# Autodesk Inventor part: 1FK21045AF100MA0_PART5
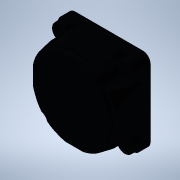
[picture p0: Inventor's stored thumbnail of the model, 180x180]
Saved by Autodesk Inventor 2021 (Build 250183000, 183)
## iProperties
Created: 2025-04
Part Number: 1FK21045AF100MA0_PART5
Material: Generic
Catalog Web Link: www.3dfindit.com
Description: -Servo synchronous motor
Document SubType Name: Modeling
Designer: psAdmin
Mass: 3.92604 g
Surface Area: 17.9521 cm^2
Volume: 3.92604 cm^3
Density: 1 g/cm^3
Appearance: PSOLRGB-48-56-69
Category: PARTsolutions
Title: 1FK21045AF100MA0_PART5
Author: Cadenas PARTsolutions
Comments: Servo synchronous motor
Sending System: PARTsolutions
Preprocessor: ST-DEVELOPER v19.3
PSOL_IDENT_0: {$CADENAS_DATA/23d-libs/siemens_ag/_cat_/52/6b/1fk21045af100ma0.prj},213 {VTYP=3D},{NB=1FK21045AF100
PSOL_IDENT_1: MA0_PART5},{LINA=1FK21045AF100MA0_PART5},{NN=1FK21045AF100MA0_PART5},{NOPRJ=TRUE},{DATE=19.08.2025 1
PSOL_IDENT_2: 4:00:38},{GEOMDATE=30.07.2025 02:01:45},{VERSION=},{LINEID=10},{WBVAR=},{WBNUMERIC=}  {NB=1FK21045AF
PSOL_IDENT_3: 100MA0_PART5},{LINA=1FK21045AF100MA0_PART5},{KT=DUMMY},{PREVIEW=../../../_pool_/cb/72/p_d211_xx_0043
PSOL_IDENT_4: 4j.png},{DESCSHORT=SIMOTICS S-1FK2 HD, SINAMICS S210 3AC 400V-480V, 2.4 Nm, 3000 rpm},{DESCLONG=SIMO
PSOL_IDENT_5: TICS S-1FK2 HD servo motor M0=2.4 Nm; PN = 0.75 kW at nN=3000 rpm (380-480 V); PN = 0.375 kW at nN=1
PSOL_IDENT_6: 500 rpm (200-240 V); with holding brake; degree of protection IP64; cylindrical shaft D19x40mm; abso
PSOL_IDENT_7: lute encoder 22-bit + 12-bit multiturn (encoder AM22DQC); with OCC interface; plug size M17, rotatab
PSOL_IDENT_8: le; SIMOTICS S-1FK2 servomotorfor a wide range of uses in industrial environments. SIMOTICS S‑1FK2 s
PSOL_IDENT_9: ervomotors are compact synchronous motors with a high dynamic performance that set themselves apart
PSOL_IDENT_10: as a result of their high power density, degree of protection and overload capability. The motors ar
PSOL_IDENT_11: e available in two variants: as High Dynamic variant (highest dynamic performance as a result of the
PSOL_IDENT_12: low intrinsic moment of inertia for applications demanding a high dynamic performance with low move
PSOL_IDENT_13: d masses) - and as Compact variant (precise and stable closed-loop control for medium up to large mo
PSOL_IDENT_14: ved masses as a result of a medium intrinsic moment of inertia). SIMOTICSS‑1FK2 servomotors fully ex
PSOL_IDENT_15: ploit their strengths in a system with the SINAMICSS210 frequency converter and simple connection us
PSOL_IDENT_16: ing the one cable connection (OCC). Advantages include the short control and positioning times, fast
PSOL_IDENT_17: and precise correction of disturbing quantities as well as stable control with a high dynamic perfo
PSOL_IDENT_18: rmance. The servo motors can be configured to address a wide range of requirements. For example with
PSOL_IDENT_19: and without holding brake, IP64 or IP65 degree of protection, singleturn or multiturn absolute enco
PSOL_IDENT_20: ders - to name just a few. Further, the servomotors are available in different shaft heights extendi
PSOL_IDENT_21: ng from 20 to 100. A shaft sealing ring is available to achieve an IP65 degree of protection and for
PSOL_IDENT_22: subsequent mounting at the motor or as spare part. SIMOTICS - the optimum motor for each and every
PSOL_IDENT_23: motion control application.},{INTNO=804766906411},{SUPPLIERALTNO=1FK2104-5AF10-0MA0},{MANUID=1FK2104
PSOL_IDENT_24: 5AF100MA0},{MANUNAME=Siemens},{MANUTYPEDESC=Synchronous motor 1FK2-HD 2.4 NM},{AAU732=SIMOTICS},{AAO
PSOL_IDENT_25: 057=S-1FK2},{AAU734=SIMOTICS S-1FK2 HD servo motor M0=2.4 Nm; PN = 0.75 kW at nN=3000 rpm (380-480 V
PSOL_IDENT_26: ); PN = 0.375 kW at nN=1500 rpm (200-240 V); with holding brake; degree of protection IP64; cylindri
PSOL_IDENT_27: cal shaft D19x40mm; absolute encoder 22-bit + 12-bit multiturn (encoder AM22DQC); with OCC interface
PSOL_IDENT_28: ; plug size M17, rotatable;},{AAW338=Synchronous motor 1FK2-HD 2.4 NM},{AAO742=SIMOTICS},{AAO663=404
PSOL_IDENT_29: 2948693070},{NOCUPEROU=1},{PRICEQUANTITY=1},{QUANTITYMIN=1},{QUANTITYINT=1},{CTN=85015100},{COO=DE},
PSOL_IDENT_30: {AAO676=1FK2104-5AF10-0MA0},{AAO677=Siemens AG},{ORDERUNIT=C62},{CONTENTUNIT=C62}
NB: 1FK21045AF100MA0_PART5
NT: Servo synchronous motor
NBSYN: $MANUID._PART5
LINA: 1FK21045AF100MA0_PART5
CATALOG: SIEMENS
PREVIEW: ../../../_pool_/cb/72/p_d211_xx_00434j.png
DESCSHORT: SIMOTICS S-1FK2 HD, SINAMICS S210 3AC 400V-480V, 2.4 Nm, 3000 rpm
DESCLONG: SIMOTICS S-1FK2 HD servo motor M0=2.4 Nm; PN = 0.75 kW at nN=3000 rpm (380-480 V); PN = 0.375 kW at nN=1500 rpm (200-240 V); with holding brake; degree of prote
INTNO: 804766906411
SUPPLIERALTNO: 1FK2104-5AF10-0MA0
MANUID: 1FK21045AF100MA0
MANUNAME: Siemens
MANUTYPEDESC: Synchronous motor 1FK2-HD 2.4 NM
AAU732: SIMOTICS
AAO057: S-1FK2
AAU734: SIMOTICS S-1FK2 HD servo motor M0=2.4 Nm; PN = 0.75 kW at nN=3000 rpm (380-480 V); PN = 0.375 kW at nN=1500 rpm (200-240 V); with holding brake; degree of prote
AAW338: Synchronous motor 1FK2-HD 2.4 NM
AAO742: SIMOTICS
AAO663: 4042948693070.0
NOCUPEROU: 1
PRICEQUANTITY: 1
QUANTITYMIN: 1
QUANTITYINT: 1
CTN: 85015100
COO: DE
ARTICLENO: 1FK21045AF100MA0_PART5
BOMINFO: 1FK21045AF100MA0_PART5
CREATOR: CADENAS GmbH
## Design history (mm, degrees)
feature "2025_04_17_15_34_52_0255"
body "Solid1"
